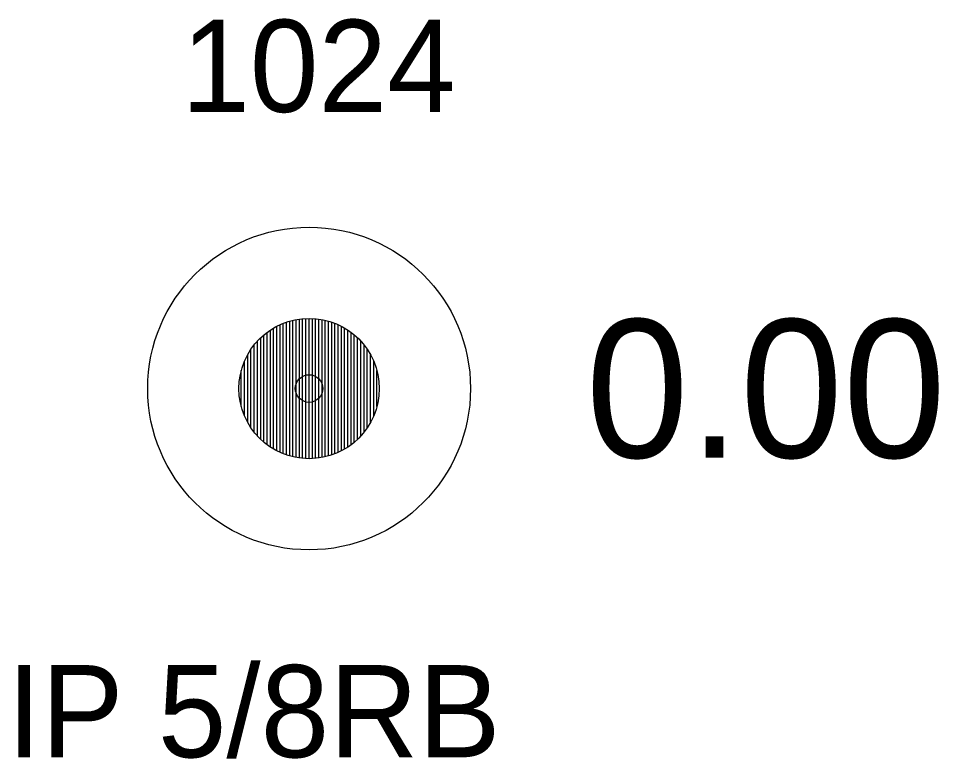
# Model space of a CAD drawing. Extents: x 1393163 to 1398407, y 1072670 to 1074651.
# Drawn here: x 1397493.63 to 1397503.61, y 1073698.07 to 1073706.1 of the extents above; entities that cross this region are included whole.
import ezdxf

# ---------------------------------------------------------------- set-up
doc = ezdxf.new("R2010")
doc.units = 0
for name, color, linetype in [('RD_EX_DV_Prop_txCode', 7, 'Continuous'), ('RD_EX_DV_PropPin', 7, 'Continuous'), ('RD_EX_TX_DV_Prop_ELEV', 7, 'Continuous'), ('RD_SMD_Locator', 7, 'Continuous')]:
    doc.layers.add(name, color=color, linetype=linetype)

msp = doc.modelspace()

# ---------------------------------------------------------------- linework, layer by layer
at = {"layer": 'RD_EX_DV_PropPin'}
for p, q in [((1397496.4672, 1073701.3905), (1397496.4672, 1073702.7759)), ((1397496.5022, 1073701.3756), (1397496.5022, 1073702.7908)), ((1397496.5372, 1073701.3627), (1397496.5372, 1073702.8037)), ((1397496.5722, 1073701.3518), (1397496.5722, 1073702.8146)), ((1397496.6072, 1073701.3426), (1397496.6072, 1073702.8238)), ((1397496.6422, 1073701.3352), (1397496.6422, 1073702.8312)), ((1397496.6772, 1073701.3295), (1397496.6772, 1073702.8369)), ((1397496.7123, 1073701.3254), (1397496.7123, 1073702.841)), ((1397496.7473, 1073701.323), (1397496.7473, 1073702.8434)), ((1397496.7823, 1073701.3222), (1397496.7823, 1073702.8442)), ((1397496.8173, 1073701.323), (1397496.8173, 1073702.8434)), ((1397496.8523, 1073701.3254), (1397496.8523, 1073702.841)), ((1397496.8873, 1073701.3295), (1397496.8873, 1073702.8369)), ((1397496.9223, 1073701.3352), (1397496.9223, 1073702.8312)), ((1397496.9573, 1073701.3426), (1397496.9573, 1073702.8238)), ((1397496.9924, 1073701.3518), (1397496.9924, 1073702.8146)), ((1397497.0274, 1073701.3627), (1397497.0274, 1073702.8037)), ((1397497.0624, 1073701.3756), (1397497.0624, 1073702.7908)), ((1397497.0974, 1073701.3905), (1397497.0974, 1073702.7759)), ((1397496.3271, 1073701.4733), (1397496.3271, 1073702.6931)), ((1397496.3621, 1073701.4487), (1397496.3621, 1073702.7177)), ((1397496.3971, 1073701.4268), (1397496.3971, 1073702.7396)), ((1397496.4321, 1073701.4075), (1397496.4321, 1073702.7589)), ((1397497.1324, 1073701.4075), (1397497.1324, 1073702.7589)), ((1397497.1674, 1073701.4268), (1397497.1674, 1073702.7396)), ((1397497.2024, 1073701.4487), (1397497.2024, 1073702.7177)), ((1397497.2375, 1073701.4733), (1397497.2375, 1073702.6931)), ((1397496.2221, 1073701.5681), (1397496.2221, 1073702.5983)), ((1397496.2571, 1073701.5325), (1397496.2571, 1073702.6339)), ((1397496.2921, 1073701.5011), (1397496.2921, 1073702.6653)), ((1397497.2725, 1073701.5011), (1397497.2725, 1073702.6653)), ((1397497.3075, 1073701.5325), (1397497.3075, 1073702.6339)), ((1397497.3425, 1073701.5681), (1397497.3425, 1073702.5983)), ((1397496.152, 1073701.6567), (1397496.152, 1073702.5097)), ((1397496.187, 1073701.609), (1397496.187, 1073702.5574)), ((1397497.3775, 1073701.609), (1397497.3775, 1073702.5574)), ((1397497.4125, 1073701.6567), (1397497.4125, 1073702.5097)), ((1397496.082, 1073701.7853), (1397496.082, 1073702.3811)), ((1397496.117, 1073701.7137), (1397496.117, 1073702.4527)), ((1397497.4475, 1073701.7137), (1397497.4475, 1073702.4527)), ((1397497.4826, 1073701.7853), (1397497.4826, 1073702.3811)), ((1397496.047, 1073701.887), (1397496.047, 1073702.2794)), ((1397497.5176, 1073701.887), (1397497.5176, 1073702.2794))]:
    msp.add_line(p, q, dxfattribs=at)
for radius in [1.75, 0.761]:
    msp.add_circle((1397496.7823, 1073702.0832), radius, dxfattribs=at)
at = {"layer": 'RD_SMD_Locator'}
msp.add_circle((1397496.7823, 1073702.0832), 0.15, dxfattribs=at)

# ---------------------------------------------------------------- texts
at = {"layer": 'RD_EX_DV_Prop_txCode'}
for s, p in [('1024', (1397495.3965, 1073705.0832)), ('IP 5/8RB', (1397493.5067, 1073698.0832))]:
    msp.add_text(s, height=1, dxfattribs=at).set_placement(p)
at = {"layer": 'RD_EX_TX_DV_Prop_ELEV'}
msp.add_text('0.00', height=1.5, dxfattribs=at).set_placement((1397499.7823, 1073701.3332))

doc.saveas('drawing.dxf')
